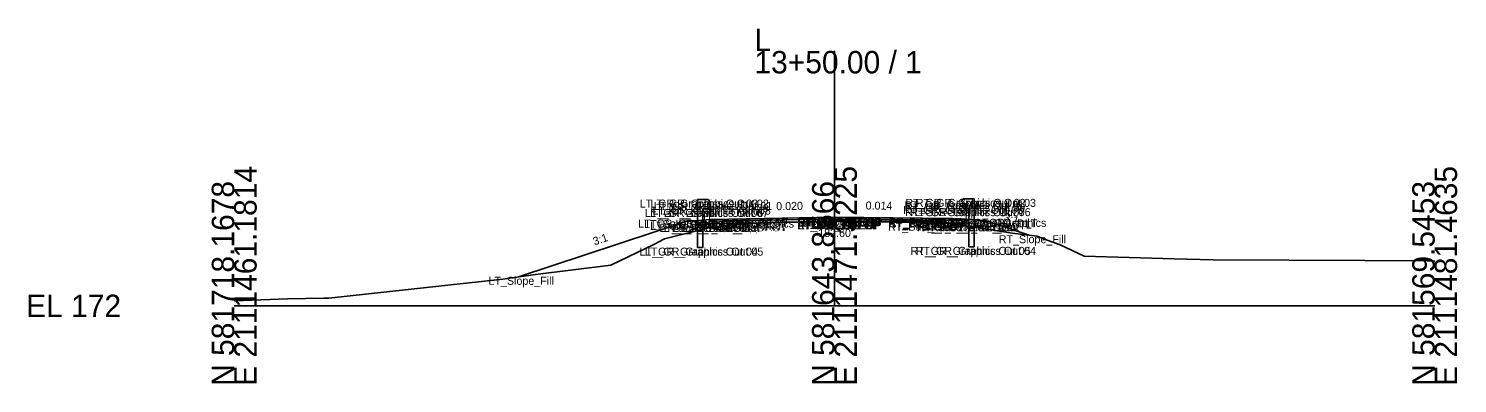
# Model space of a CAD drawing. Extents: x -486 to 1153, y -333 to 9539.
# Drawn here: x -25.7 to 152.8, y 2990.3 to 3034.7 of the extents above; entities that cross this region are included whole.
import ezdxf

# ---------------------------------------------------------------- set-up
doc = ezdxf.new("R2010")
doc.units = 0
for name, color, linetype in [('Default', 7, 'Continuous'), ('Exist Cross Section Cell', 7, 'Continuous'), ('Exist XS Ground Line', 7, 'Continuous'), ('Prop CMT Guardrail Graphics', 7, 'Continuous'), ('Prop CMT Pvmt Course 1', 7, 'Continuous'), ('Prop CMT Pvmt Course 2', 7, 'Continuous'), ('Prop CMT Pvmt Course 3', 7, 'Continuous'), ('Prop CMT Pvmt Surface', 7, 'Continuous'), ('Prop CMT Pvmt Surface Shoulder', 7, 'Continuous'), ('Prop CMT Shld Paved Course 1', 7, 'Continuous'), ('Prop CMT Shld Paved Course 2', 7, 'Continuous'), ('Prop CMT Shld Paved Course 3', 7, 'Continuous'), ('Prop CMT Slope Grass', 7, 'Continuous'), ('Prop CMT Subgrade Earthwork', 7, 'Continuous'), ('Prop XS Earthwork Shape', 7, 'Continuous'), ('Prop XS SE Text', 7, 'Continuous'), ('Prop XS Side Slope Text', 7, 'Continuous'), ('Scratch_Level_0', 7, 'Continuous')]:
    doc.layers.add(name, color=color, linetype=linetype)

msp = doc.modelspace()

# ---------------------------------------------------------------- linework, layer by layer
at = {"layer": 'Exist Cross Section Cell'}
for p, q in [((75, 3000), (75, 3031.85)), ((0, 3000), (75, 3000)), ((75, 3000), (150, 3000))]:
    msp.add_line(p, q, dxfattribs=at)
at = {"layer": 'Exist XS Ground Line'}
for p, q in [((60.26, 3009.92), (64.5, 3010.29)), ((64.5, 3010.29), (65.7, 3010.33)), ((65.7, 3010.33), (73.94, 3010.6)), ((73.94, 3010.6), (75, 3010.6)), ((75, 3010.6), (82.58, 3010.6)), ((82.58, 3010.6), (83.87, 3010.59)), ((83.87, 3010.59), (85.05, 3010.62)), ((85.05, 3010.62), (88.48, 3010.48)), ((88.48, 3010.48), (97.19, 3009.09)), ((52.43, 3007.67), (53.78, 3008.38)), ((53.78, 3008.38), (59.31, 3009.74)), ((59.31, 3009.74), (60.26, 3009.92)), ((97.19, 3009.09), (100.34, 3008.72)), ((100.34, 3008.72), (101.11, 3008.38)), ((101.11, 3008.38), (103.19, 3007.63)), ((47.06, 3005.07), (52.43, 3007.67)), ((103.19, 3007.63), (106.21, 3006.23)), ((37.63, 3003.94), (47.06, 3005.07)), ((106.21, 3006.23), (117.45, 3005.88)), ((117.45, 3005.88), (122.33, 3005.75)), ((122.33, 3005.75), (141.29, 3005.65)), ((141.29, 3005.65), (149.08, 3005.63)), ((149.08, 3005.63), (150, 3005.59)), ((11.83, 3000.97), (33.55, 3003.33)), ((33.55, 3003.33), (37.63, 3003.94)), ((0, 3000.64), (6.67, 3000.86)), ((6.67, 3000.86), (11.19, 3000.96)), ((11.19, 3000.96), (11.83, 3000.97))]:
    msp.add_line(p, q, dxfattribs=at)
at = {"layer": 'Prop CMT Guardrail Graphics'}
for points in [[(57.88, 3007.28), (57.88, 3013.28)], [(57.88, 3013.28), (59.21, 3013.28), (59.48, 3012.99)], [(59.48, 3012.41), (59.21, 3012.12), (58.55, 3012.12)], [(58.55, 3012.12), (58.55, 3007.28)], [(59.48, 3012.99), (59.21, 3012.7)], [(59.21, 3012.7), (59.48, 3012.41)], [(92.45, 3013.37), (91.12, 3013.37), (90.84, 3013.08)], [(90.84, 3013.08), (91.12, 3012.79)], [(91.12, 3012.79), (90.84, 3012.5)], [(90.84, 3012.5), (91.12, 3012.21), (91.78, 3012.21)], [(91.78, 3012.21), (91.78, 3007.37)], [(92.45, 3007.37), (92.45, 3013.37)], [(58.55, 3007.28), (57.88, 3007.28)], [(91.78, 3007.37), (92.45, 3007.37)]]:
    msp.add_lwpolyline(points, dxfattribs=at)
at = {"layer": 'Prop CMT Pvmt Course 1'}
for points in [[(75, 3011.1), (64, 3010.88)], [(64, 3010.67), (75, 3010.89)], [(64, 3010.88), (64, 3010.67)], [(75, 3010.89), (75, 3011.1)], [(75, 3011.1), (86, 3010.95)], [(75, 3010.89), (75, 3011.1)], [(86, 3010.74), (75, 3010.89)], [(86, 3010.95), (86, 3010.74)]]:
    msp.add_lwpolyline(points, dxfattribs=at)
msp.add_lwpolyline([(75, 3010.89), (75, 3010.97), (75, 3010.97), (75, 3010.89)], close=True, dxfattribs=at)
msp.add_lwpolyline([(75, 3010.89), (75, 3010.97), (75, 3010.97), (75, 3010.89)], close=True, dxfattribs=at)
at = {"layer": 'Prop CMT Pvmt Course 2'}
for points in [[(75, 3010.89), (64, 3010.67)], [(64, 3010.67), (64, 3010.34)], [(64, 3010.34), (75, 3010.56)], [(75, 3010.56), (75, 3010.89)], [(75, 3010.56), (75, 3010.89)], [(75, 3010.89), (86, 3010.74)], [(86, 3010.4), (75, 3010.56)], [(86, 3010.74), (86, 3010.4)]]:
    msp.add_lwpolyline(points, dxfattribs=at)
at = {"layer": 'Prop CMT Pvmt Course 3'}
for points in [[(75, 3010.56), (64, 3010.34)], [(64, 3010.34), (64, 3010.34)], [(75, 3010.56), (75, 3010.56)], [(75, 3010.56), (86, 3010.4)], [(75, 3010.56), (75, 3010.56)], [(86, 3010.4), (86, 3010.4)]]:
    msp.add_lwpolyline(points, dxfattribs=at)
at = {"layer": 'Prop CMT Pvmt Surface'}
for points in [[(75, 3011.1), (64, 3010.88)], [(75, 3011.1), (86, 3010.95)]]:
    msp.add_lwpolyline(points, dxfattribs=at)
at = {"layer": 'Prop CMT Pvmt Surface Shoulder'}
for points in [[(64, 3010.88), (59.58, 3010.79)], [(86, 3010.95), (90.74, 3010.88)]]:
    msp.add_lwpolyline(points, dxfattribs=at)
at = {"layer": 'Prop CMT Shld Paved Course 1'}
for points in [[(64, 3010.88), (59.58, 3010.79), (59.37, 3010.58)], [(59.37, 3010.58), (64, 3010.67)], [(64, 3010.67), (64, 3010.88)], [(86, 3010.95), (90.74, 3010.88), (90.96, 3010.67)], [(86, 3010.74), (86, 3010.95)], [(90.96, 3010.67), (86, 3010.74)]]:
    msp.add_lwpolyline(points, dxfattribs=at)
at = {"layer": 'Prop CMT Shld Paved Course 2'}
for points in [[(64, 3010.67), (59.37, 3010.58), (59.03, 3010.24)], [(59.03, 3010.24), (64, 3010.34)], [(64, 3010.34), (64, 3010.67)], [(86, 3010.74), (90.96, 3010.67), (91.29, 3010.33)], [(86, 3010.4), (86, 3010.74)], [(91.29, 3010.33), (86, 3010.4)]]:
    msp.add_lwpolyline(points, dxfattribs=at)
at = {"layer": 'Prop CMT Shld Paved Course 3'}
for points in [[(64, 3010.34), (59.03, 3010.24)], [(59.03, 3010.24), (59.03, 3010.24), (59.03, 3010.24)], [(64, 3010.34), (64, 3010.34)], [(86, 3010.4), (91.29, 3010.33)], [(86, 3010.4), (86, 3010.4)], [(91.29, 3010.33), (91.29, 3010.33), (91.29, 3010.33)]]:
    msp.add_lwpolyline(points, dxfattribs=at)
at = {"layer": 'Prop CMT Slope Grass'}
for points in [[(56.48, 3010.54), (35.53, 3003.63)], [(59.48, 3010.78), (56.48, 3010.54)], [(59.58, 3010.79), (59.48, 3010.78)], [(90.74, 3010.88), (90.84, 3010.87)], [(90.84, 3010.87), (93.84, 3010.65)], [(93.84, 3010.65), (99.35, 3008.83)]]:
    msp.add_lwpolyline(points, dxfattribs=at)
at = {"layer": 'Prop CMT Subgrade Earthwork'}
for points in [[(59.03, 3010.24), (58.56, 3010.71)], [(64, 3010.34), (59.03, 3010.24)], [(75, 3010.56), (64, 3010.34)], [(75, 3010.56), (86, 3010.4)], [(86, 3010.4), (91.29, 3010.33)], [(91.29, 3010.33), (91.77, 3010.8)]]:
    msp.add_lwpolyline(points, dxfattribs=at)
at = {"layer": 'Prop XS Earthwork Shape'}
for points in [[(59.03, 3010.24), (58.56, 3010.71), (56.48, 3010.54), (35.53, 3003.63), (37.63, 3003.94), (47.06, 3005.07), (52.43, 3007.67), (53.78, 3008.38), (59.31, 3009.74), (60.26, 3009.92), (64.5, 3010.29), (65.7, 3010.33), (69.1, 3010.44), (64, 3010.34)], [(75, 3010.56), (86, 3010.4), (89.23, 3010.36), (88.48, 3010.48), (85.05, 3010.62), (83.87, 3010.59), (82.58, 3010.6), (75, 3010.6), (73.94, 3010.6), (69.1, 3010.44)], [(91.77, 3010.8), (93.84, 3010.65), (99.35, 3008.83), (97.19, 3009.09), (89.23, 3010.36), (91.29, 3010.33)]]:
    msp.add_lwpolyline(points, close=True, dxfattribs=at)

# ---------------------------------------------------------------- texts
at = {"layer": 'Default'}
for s, height, p in [('182.60', 1, (72.97, 3008.6)), ('-', 0.0001, (0, 3000))]:
    msp.add_text(s, height=height, dxfattribs=at).set_placement(p)
at = {"layer": 'Exist Cross Section Cell'}
for s, p in [('L', (65, 3031.85)), ('13+50.00 / 1', (65, 3029.05)), ('EL 172', (-26, 2998.6))]:
    msp.add_text(s, height=2.8, dxfattribs=at).set_placement(p)
for s, p in [('E 2111461.1814', (2.8, 2990)), ('E 2111471.3225', (77.8, 2990)), ('E 2111481.4635', (152.8, 2990)), ('N 581718.1678', (0, 2990)), ('N 581643.8566', (75, 2990)), ('N 581569.5453', (150, 2990))]:
    msp.add_text(s, height=2.8, rotation=90, dxfattribs=at).set_placement(p)
at = {"layer": 'Prop XS SE Text'}
for s, rotation, p in [('0.020', 1.1458, (67.73, 3011.95)), ('0.014', 359.1979, (78.89, 3012.05))]:
    msp.add_text(s, height=1, rotation=rotation, dxfattribs=at).set_placement(p)
at = {"layer": 'Prop XS Side Slope Text'}
for rotation, p in [(341.7371, (96.08, 3010.7)), (18.2629, (45.02, 3007.55))]:
    msp.add_text('3:1', height=1, rotation=rotation, dxfattribs=at).set_placement(p)
at = {"layer": 'Scratch_Level_0'}
for s, p in [('LT_GR_Graphics Out 03', (50.66, 3012.28)), ('LT_GR_Graphics Out 06', (51.32, 3011.12)), ('LT_GR_Graphics Out 07', (51.97, 3011.12)), ('LT_GR_Graphics Out 09', (51.99, 3011.7)), ('LT_GR_Graphics Out 02', (52.01, 3012.28)), ('LT_GR_Graphics Out 08', (52.25, 3011.41)), ('LT_GR_Graphics Out 01', (52.43, 3011.99)), ('RT_GR_Graphics Out 08', (83.56, 3011.5)), ('RT_GR_Graphics Out 01', (83.73, 3012.08)), ('RT_GR_Graphics Out 07', (83.81, 3011.21)), ('RT_GR_Graphics Out 09', (83.83, 3011.79)), ('RT_GR_Graphics Out 02', (83.86, 3012.37)), ('RT_GR_Graphics Out 06', (84.5, 3011.21)), ('RT_GR_Graphics Out 03', (85.17, 3012.37)), ('LT_GS_OS_GR_Face_Graphics', (50.48, 3009.78)), ('LT_Sub_Trench_Out_DLT', (51.21, 3009.71)), ('LT_GS_OS_CTL', (51.95, 3009.54)), ('LT_Sub_Trench_Out', (53.14, 3009.24)), ('LT_PS3_Shelf_Out', (53.69, 3009.24)), ('LT_PS3_OEOP', (54.82, 3009.24)), ('LT_PS2_OEOP', (55.16, 3009.58)), ('LT_PS1_OEOP', (55.49, 3009.79)), ('LT_PV2_OEOT', (59.75, 3009.67)), ('LT_PV3_OEOT', (59.75, 3009.34)), ('LT_Sub_OEOT', (59.77, 3009.34)), ('LT_PV1_OEOT', (59.87, 3009.88)), ('RT_PV2_OEEOP', (70.33, 3009.89)), ('RT_PV3_OEEOP', (70.33, 3009.56)), ('RT_Sub_OEEOP', (70.36, 3009.56)), ('LT_PV2_OEEOP', (70.39, 3009.89)), ('LT_PV3_OEEOP', (70.39, 3009.56)), ('LT_Sub_OEEOP', (70.42, 3009.56)), ('RT_PV1_OEEOP', (70.45, 3009.97)), ('LT_PV1_OEEOP', (70.51, 3009.97)), ('RT_PV2_IEEOP', (70.71, 3009.89)), ('LT_PV2_IEEOP', (70.77, 3009.89)), ('RT_PV1_IEEOP', (70.83, 3009.97)), ('LT_PV1_IEEOP', (70.89, 3009.97)), ('PV2_PGL', (72.35, 3009.89)), ('PV1_PGL', (72.47, 3010.1)), ('RT_PV2_OEOT', (81.69, 3009.74)), ('RT_PV3_OEOT', (81.69, 3009.4)), ('RT_Sub_OEOT', (81.71, 3009.4)), ('RT_GS_OS_GR_Face_Graphics', (81.78, 3009.87)), ('RT_PV1_OEOT', (81.81, 3009.95)), ('RT_Sub_Trench_Out_DLT', (84.36, 3009.8)), ('RT_Sub_Trench_Out', (85.34, 3009.33)), ('RT_PS3_Shelf_Out', (85.89, 3009.33)), ('RT_PS1_OEOP', (86.59, 3009.88)), ('RT_PS2_OEOP', (86.68, 3009.67)), ('RT_PS3_OEOP', (87.02, 3009.33)), ('RT_GS_OS_CTL', (89.25, 3009.65)), ('RT_Slope_Fill', (95.53, 3007.83)), ('LT_GR_Graphics Out 04', (50.65, 3006.28)), ('LT_GR_Graphics Out 05', (51.32, 3006.28)), ('RT_GR_Graphics Out 05', (84.5, 3006.37)), ('RT_GR_Graphics Out 04', (85.16, 3006.37)), ('LT_Slope_Fill', (31.77, 3002.63))]:
    msp.add_text(s, height=1, dxfattribs=at).set_placement(p)

doc.saveas('drawing.dxf')
